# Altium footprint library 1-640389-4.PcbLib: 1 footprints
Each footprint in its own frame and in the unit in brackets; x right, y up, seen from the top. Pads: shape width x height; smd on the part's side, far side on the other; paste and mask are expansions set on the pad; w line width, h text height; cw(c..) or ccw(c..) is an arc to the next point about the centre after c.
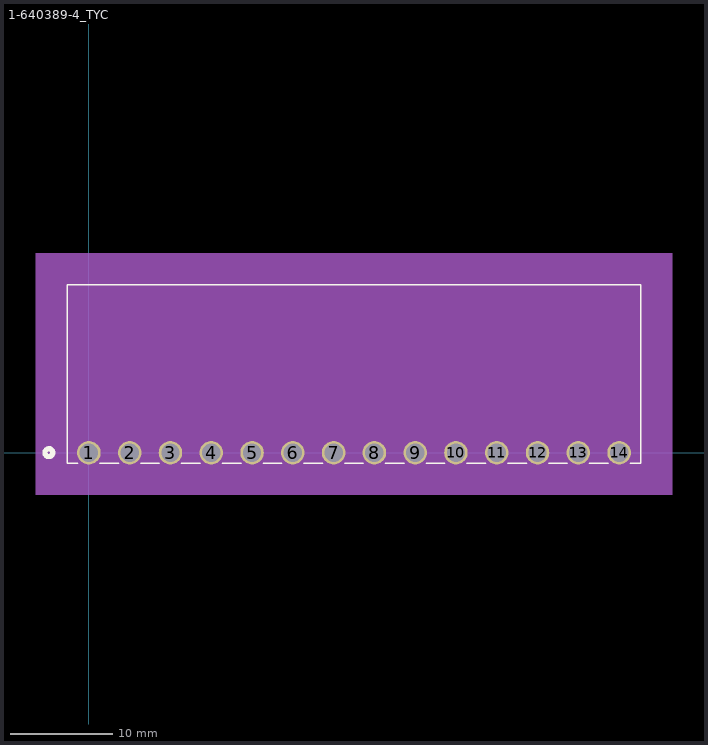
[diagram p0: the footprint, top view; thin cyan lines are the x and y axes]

## 1-640389-4_TYC [mil]
pads (14):
  round 90 hole 70 mask+0: 1(0,0) 2(156,0) 3(312,0) 4(468,0) 5(624,0) 6(780,0) 7(936,0) 8(1092,0) 9(1248,0) 10(1404,0) 11(1560,0) 12(1716,0) 13(1872,0) 14(2028,0)
Top Overlay:
  circle w20: c-153,0 r15
  lines w6: -42.14,-40 -83,-40 -83,642 2111,642 2111,-40 2070.14,-40 ; 42.14,-40 113.86,-40 ; 198.14,-40 269.86,-40 ; 354.14,-40 425.86,-40 ; 510.14,-40 581.86,-40 ; 666.14,-40 737.86,-40 ; 822.14,-40 893.86,-40 ; 978.14,-40 1049.86,-40 ; 1134.14,-40 1205.86,-40 ; 1290.14,-40 1361.86,-40 ; 1446.14,-40 1517.86,-40 ; 1602.14,-40 1673.86,-40 ; 1758.14,-40 1829.86,-40 ; 1914.14,-40 1985.86,-40
Bottom Overlay:
  circle w20: c-153,0 r15
Mechanical 5:
  region: -203,762 2231,762 2231,-160 -203,-160
Mechanical 13:
  circle w20: c0,-75 r15
  lines w1: -78,-35 2106,-35 2106,637 -78,637 -78,-35
Mechanical 15:
  region: 2116,647 -88,647 -88,-55 2116,-55
  lines w6: -88,-55 -88,647 2116,647 2116,-55 -88,-55
3D body: height 10, standoff 0, extent 0,0 10,10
